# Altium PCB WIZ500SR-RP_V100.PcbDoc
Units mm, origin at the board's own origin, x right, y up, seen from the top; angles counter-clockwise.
Board outline 50 x 30 mm, 4 copper layers (Top Layer, Internal Plane 1, Internal Plane 2, Bottom Layer); 73 components, 72 nets, 294 pads, 204 vias.
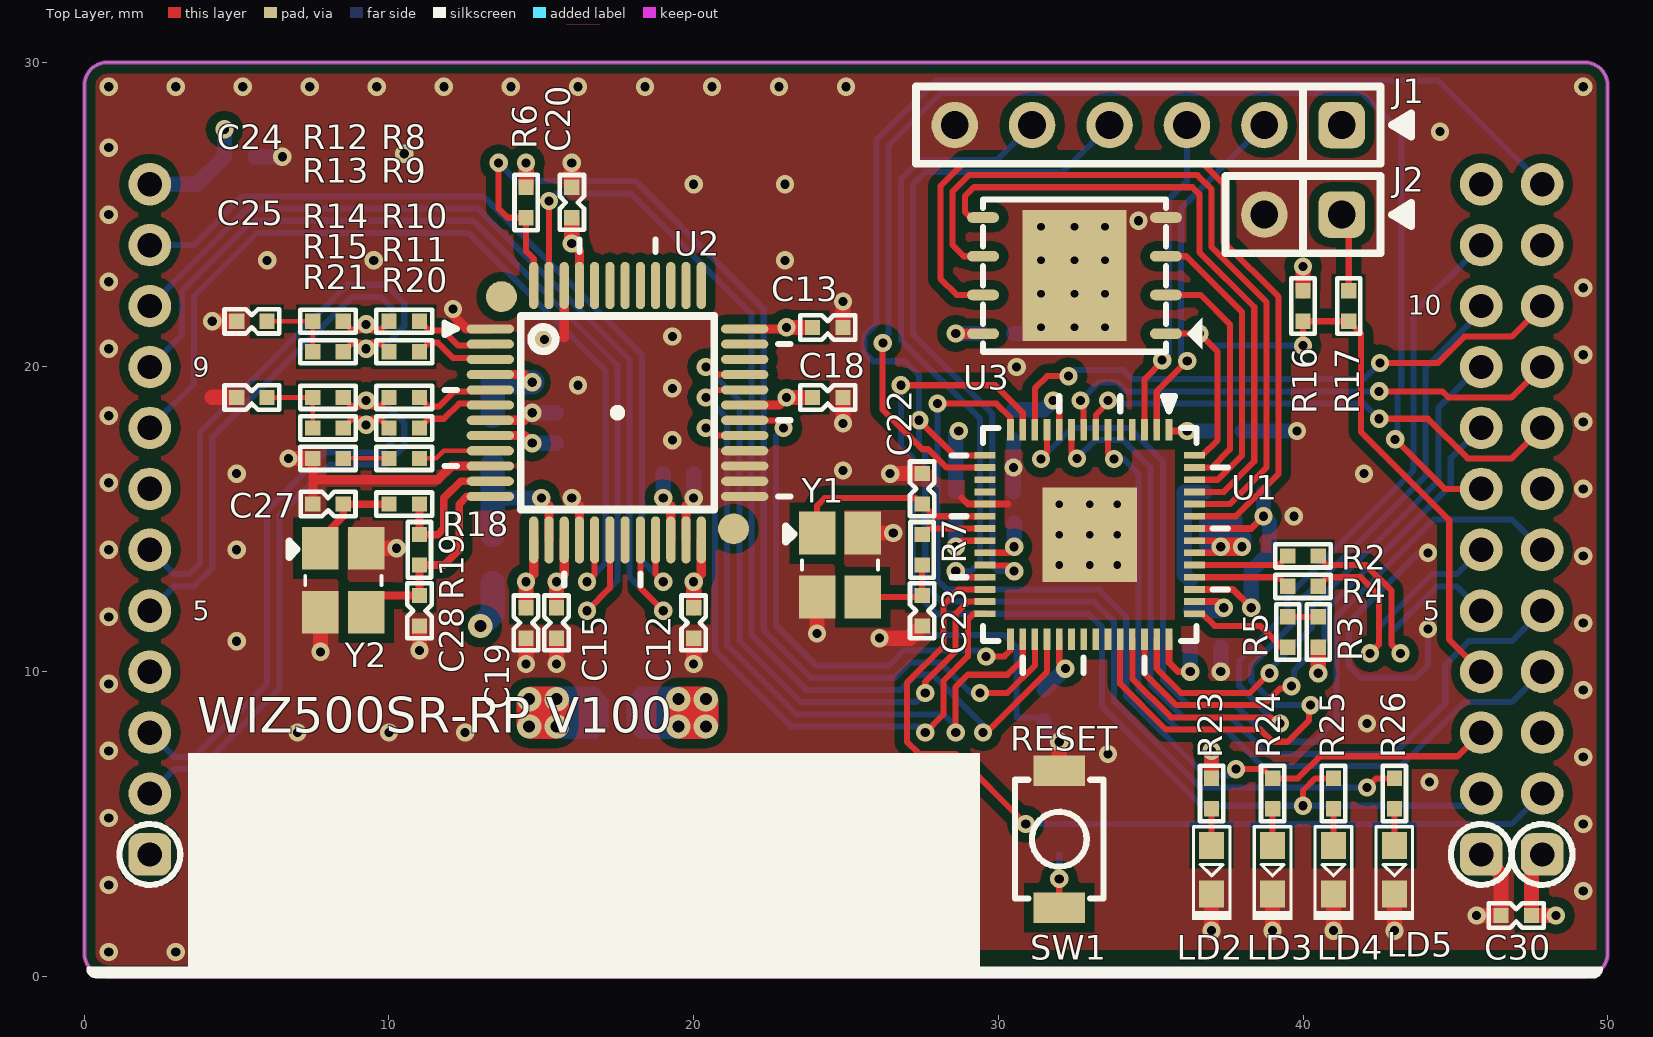
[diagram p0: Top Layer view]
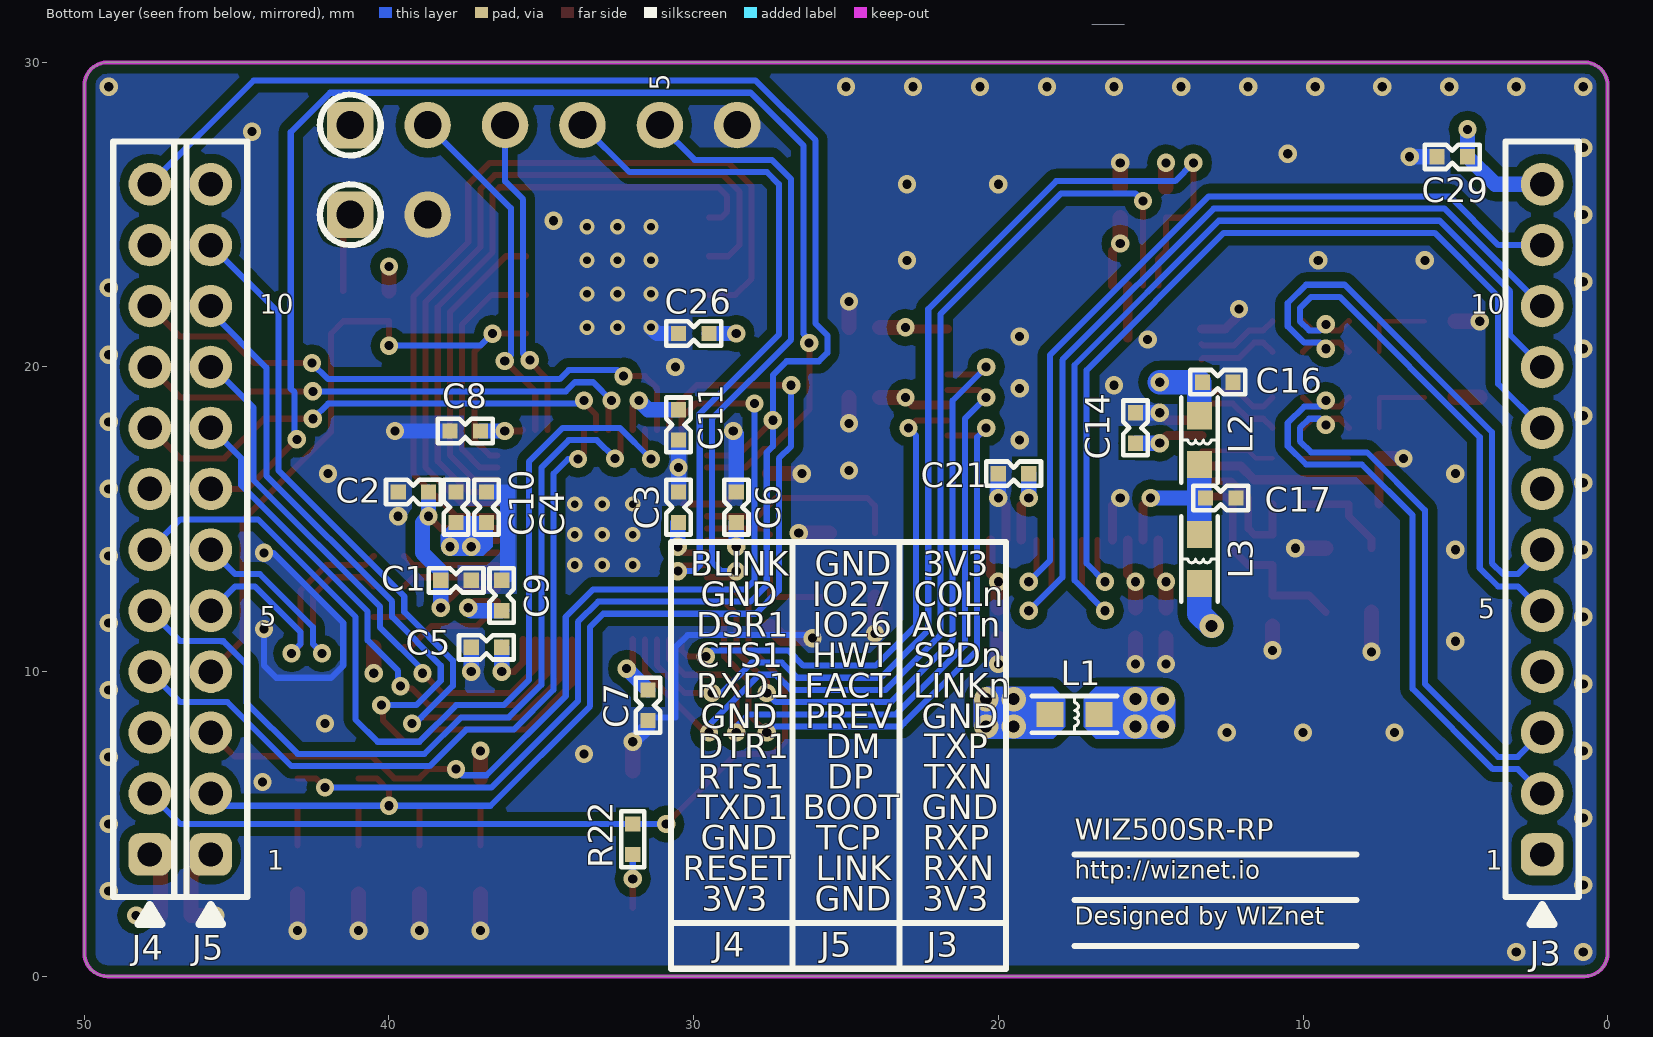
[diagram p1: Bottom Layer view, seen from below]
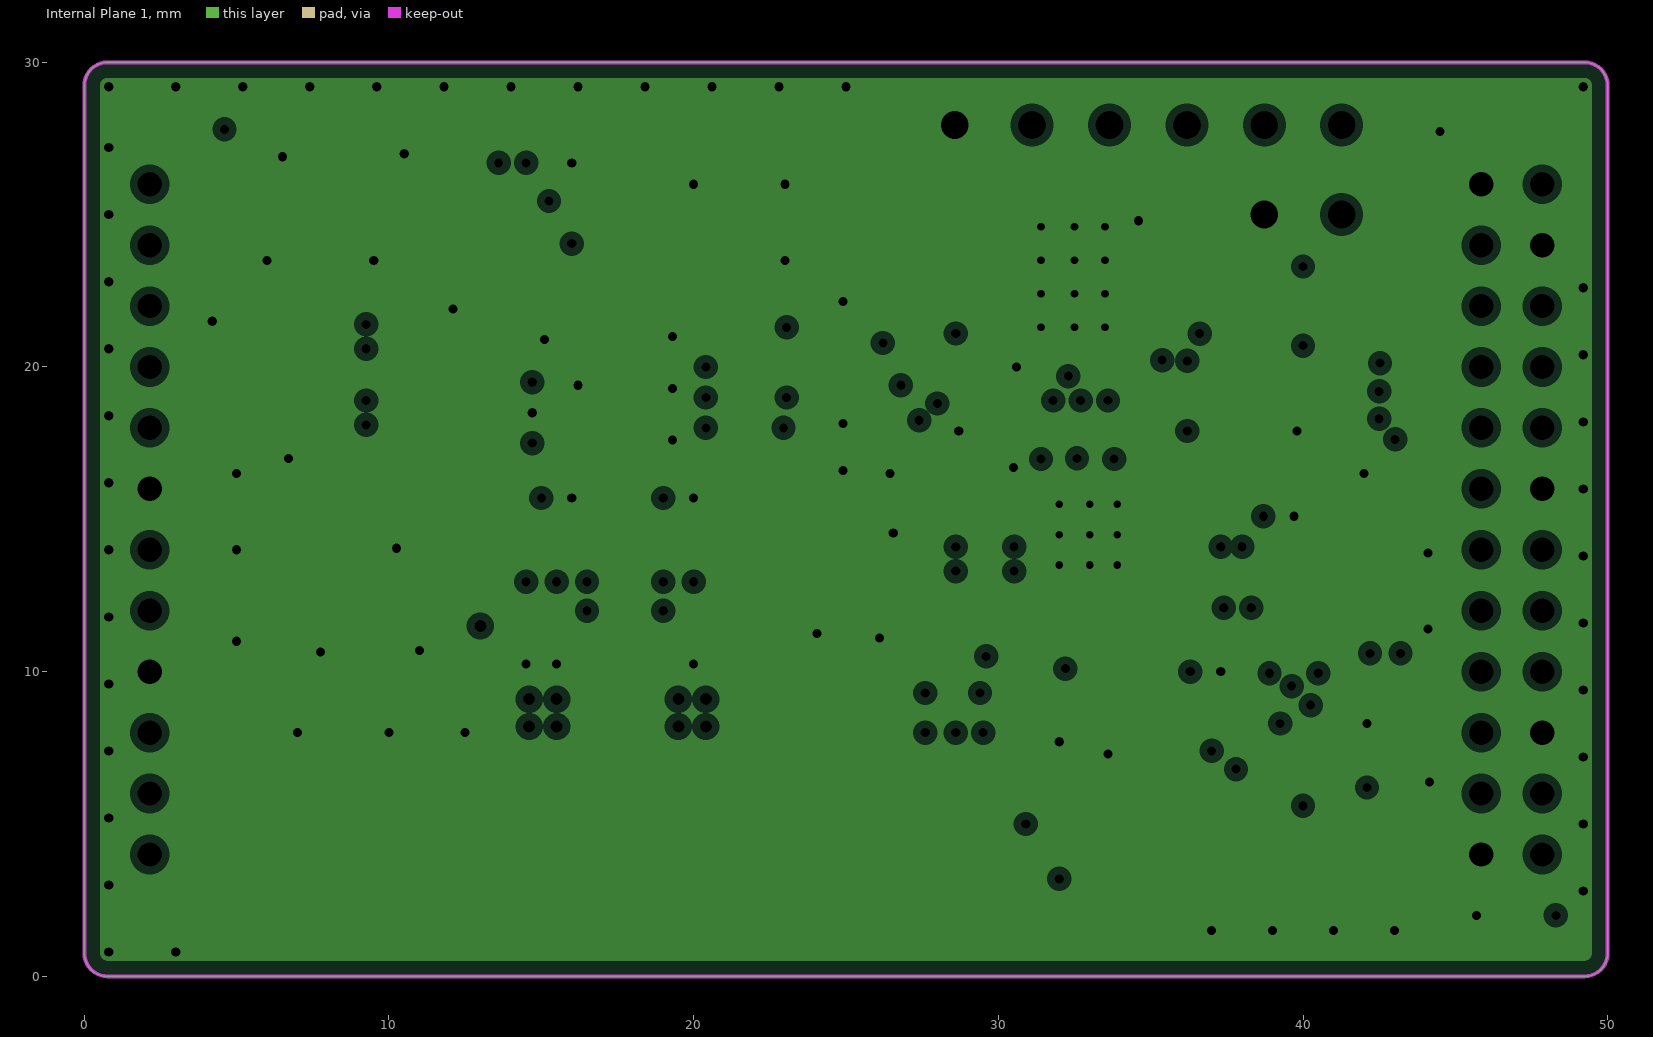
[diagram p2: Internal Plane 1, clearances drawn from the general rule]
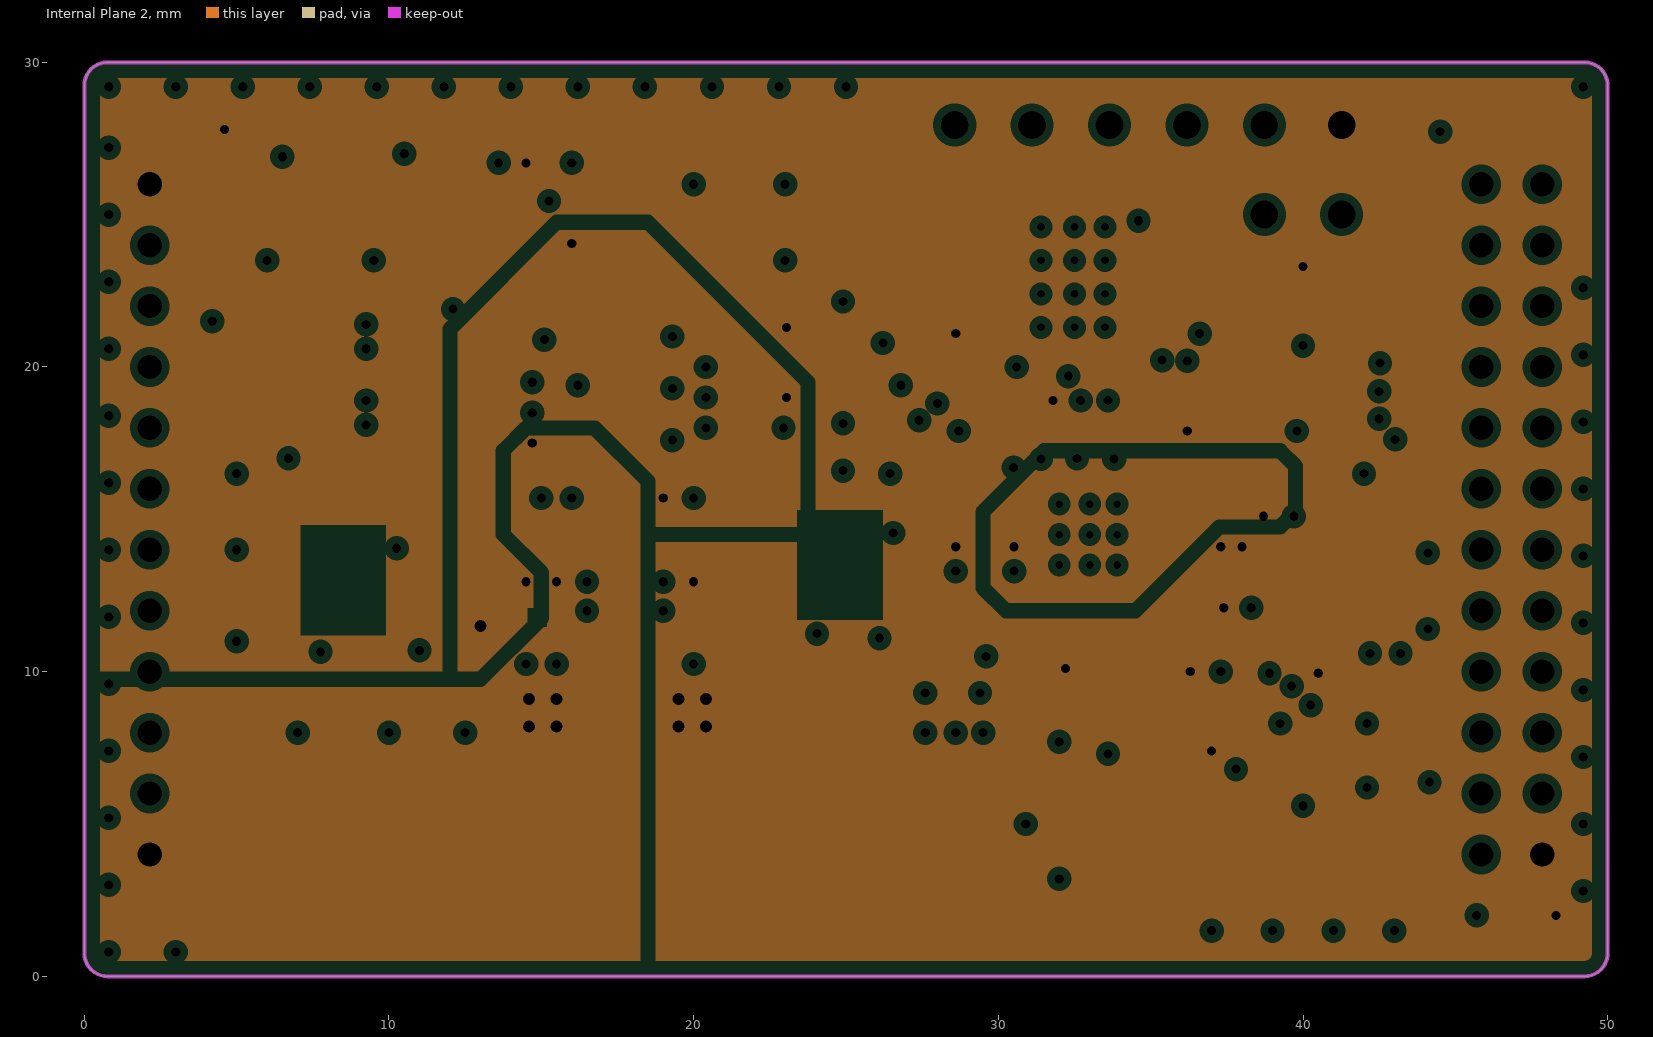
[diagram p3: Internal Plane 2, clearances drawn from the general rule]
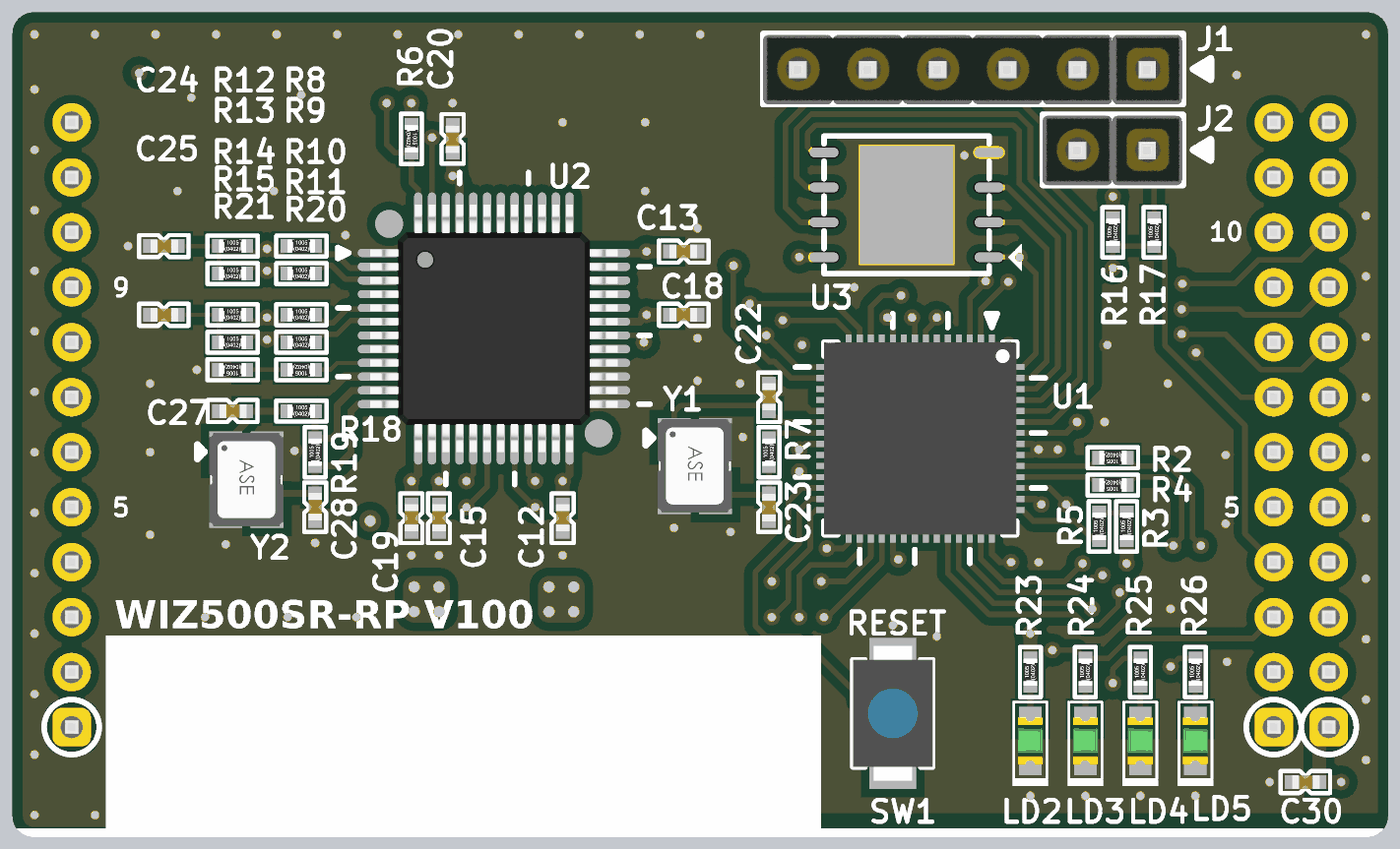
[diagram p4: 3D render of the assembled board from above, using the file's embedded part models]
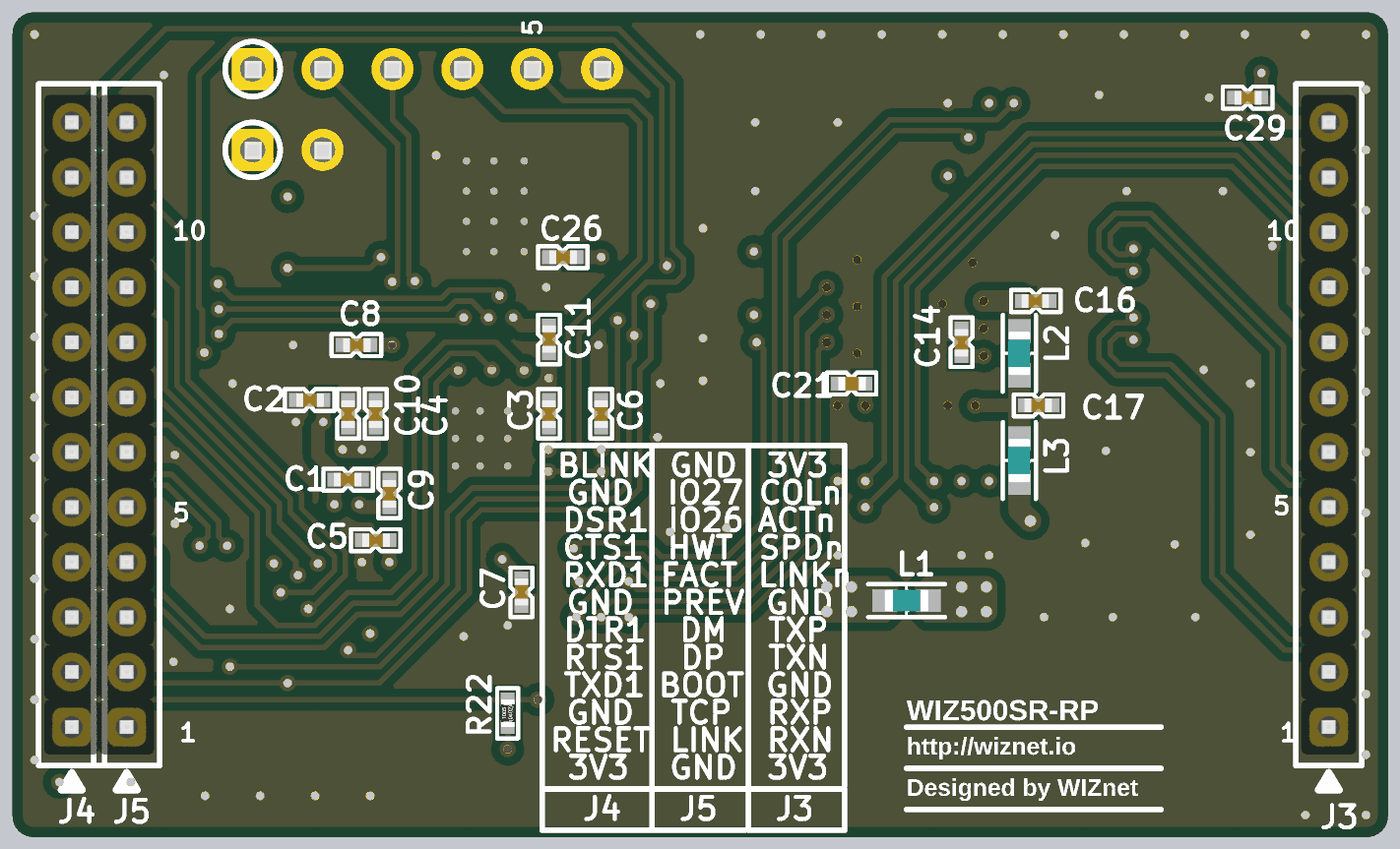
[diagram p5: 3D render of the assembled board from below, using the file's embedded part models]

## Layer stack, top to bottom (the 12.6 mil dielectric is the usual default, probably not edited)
Top Solder: solder mask 0.0102, Solder Resist, Dk 3.5
Top Layer: signal copper 0.0356
Dielectric1: core 0.32, FR-4, Dk 4.8
Internal Plane 1: plane copper 0.0356, net GND
Dielectric5: prepreg 0.32, FR-4, Dk 4.8
Internal Plane 2: plane copper 0.0356, net (Multiple Nets)
Dielectric6: core 0.32, FR-4, Dk 4.8
Bottom Layer: signal copper 0.0356
Bottom Solder: solder mask 0.0102, Solder Resist, Dk 3.5

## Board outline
0,0.762 0,29.238 cw(c0.762,29.238) 0.762,30 49.238,30 cw(c49.238,29.238) 50,29.238 50,0.762 cw(c49.238,0.762) 49.238,0 0.762,0 cw(c0.762,0.762)

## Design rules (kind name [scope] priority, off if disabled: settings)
Clearance U1 [InComponent('u1')] p1: gap=0.15 ignorepadtopadclearanceinfootprint=FALSE except(0: Arc-Hole Track-Hole SMDPad-Hole THPad-Hole Via-Hole Fill-Hole Poly-Hole Region-Hole Text-Hole; 0.3: Arc-Poly Track-Poly SMDPad-Poly THPad-Poly Via-Poly Fill-Poly Poly-Poly Poly-Region Poly-Text)
Clearance [All] p2: gap=0.2 ignorepadtopadclearanceinfootprint=FALSE except(0: Arc-Hole Track-Hole SMDPad-Hole THPad-Hole Via-Hole Fill-Hole Poly-Hole Region-Hole Text-Hole; 0.3: Arc-Poly Track-Poly SMDPad-Poly THPad-Poly Via-Poly Fill-Poly Poly-Poly Poly-Region Poly-Text)
DiffPairsRouting [All] p1: maxlimit=0.2 minlimit=0.2 mostfreqgap=0.2 toplayer_minwidth=0.2 toplayer_maxwidth=0.2 toplayer_prefwidth=0.2 bottomlayer_minwidth=0.2 bottomlayer_maxwidth=0.2 bottomlayer_prefwidth=0.2 maxuncoupledlength=15.24
HoleSize [All] p1: absolutevalues=TRUE maxlimit=4.064 minlimit=0.025 maxpercent=80.000 minpercent=20.000
PlaneClearance [All] p1: clearance=0.25
PlaneConnect [All] p1: planeconnectstyle=Direct reliefexpansion=0.508 reliefentries=4 reliefconductorwidth=0.254 reliefairgap=0.254
PolygonConnect [All] p1: connectstyle=Direct reliefconductorwidth=0.254 reliefentries=4 polygonreliefangle="90 Angle" airgapwidth=0.254
RoutingVias [All] p1: holewidth=0.3 width=0.6 viastyle="Through Hole" minholewidth=0.25 minwidth=0.5 maxholewidth=0.4 maxwidth=0.8
SolderMaskExpansion [All] p1: expansion=0 istentingtop=FALSE
Width [All] p1: maxlimit=6 minlimit=0.1 preferedwidth=0.2
26 further rules are at their usual default settings.

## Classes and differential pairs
differential pair TX: +TX_P -TX_N
differential pair RX: +RX_P -RX_N

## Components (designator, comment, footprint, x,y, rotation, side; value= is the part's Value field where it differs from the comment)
C1 "1uF" CAP-0402#1 37.8,13 r0 bottom
C2 "0.1uF" CAP-0402#1 39.2,15.9 r180 bottom
C3 "0.1uF" CAP-0402#1 30.5,15.4 r270 bottom
C4 "1uF" CAP-0402#1 36.8,15.4 r270 bottom
C5 "0.1uF" CAP-0402#1 36.8,10.8 r180 bottom
C6 "0.1uF" CAP-0402#1 28.6,15.4 r270 bottom
C7 "0.1uF" CAP-0402#1 31.5,8.9 r90 bottom
C8 "0.1uF" CAP-0402#1 37.5,17.9 r180 bottom
C9 "0.1uF" CAP-0402#1 36.3,12.5 r270 bottom
C10 "0.1uF" CAP-0402#1 37.8,15.4 r270 bottom
C11 "0.1uF" CAP-0402#1 30.5,18.1 r90 bottom
C12 "0.1uF" CAP-0402#1 20,11.6 r90 top
C13 "0.1uF" CAP-0402#1 24.4,21.3 r180 top
C14 "0.1uF" CAP-0402#1 15.5,18 r270 bottom
C15 "0.1uF" CAP-0402#1 15.5,11.6 r90 top
C16 "0.1uF" CAP-0402#1 12.8,19.5 r0 bottom
C17 "1uF" CAP-0402#1 12.7,15.7 r0 bottom
C18 "0.1uF" CAP-0402#1 24.4,19 r180 top
C19 "0.1uF" CAP-0402#1 14.5,11.6 r90 top
C20 "0.1uF" CAP-0402#1 16,25.4 r270 top
C21 "0.1uF" CAP-0402#2 19.5,16.5 r180 bottom
C22 "15pF" CAP-0402#1 27.5,16 r90 top
C23 "15pF" CAP-0402#1 27.5,12 r270 top
C24 "0.1uF" CAP-0402#1 5.5,21.5 r0 top
C25 "0.1uF" CAP-0402#1 5.5,19 r0 top
C26 "0.1uF" CAP-0402#1 30,21.1 r180 bottom
C27 "18pF" CAP-0402#1 8,15.5 r0 top
C28 "18pF" CAP-0402#1 11,12 r90 top
C29 "0.1uF" CAP-0402#1 5.1,26.9 r180 bottom
C30 "0.1uF" CAP-0402#1 47,2 r0 top
J1 "2.54mm 1x6 Pin Header DIP" IDC-1X6 41.27,27.94 r180 top
J2 "2.54mm 1x2 Pin Header DIP" IDC-1X2 41.27,25 r180 top
J3 "2.00mm 1x12 Pin Header DIP" IDC-1X12(2MM) 2.15,4 r90 bottom locked
J4 "2.00mm 1x12 Pin Header DIP" IDC-1X12(2MM) 47.85,4 r90 bottom locked
J5 "2.00mm 1x12 Pin Header DIP" IDC-1X12(2MM) 45.85,4 r90 bottom locked
L1 "HH-1M1608-121JT" IND-0603 17.5,8.6 r180 bottom
L2 "HH-1M1608-121JT" IND-0603 13.4,17.6 r270 bottom
L3 "HH-1M1608-121JT" IND-0603 13.4,13.7 r270 bottom
LD2 "Red" LED-0603-green 37,3.5 r270 top
LD3 "Green" LED-0603-GREEN 39,3.5 r270 top
LD4 "Green" LED-0603-GREEN 41,3.5 r270 top
LD5 "Green" LED-0603-GREEN 43,3.5 r270 top
R2 "0R" RES-0402#1 40,13.8 r180 top
R3 "200R" RES-0402#1 40.5,11.3 r90 top
R4 "0R" RES-0402#1 40,12.8 r180 top
R5 "1R" RES-0402#1 39.5,11.3 r90 top
R6 "4.7K" RES-0402#1 14.5,25.4 r270 top
R7 "1K" RES-0402#1 27.5,14 r90 top
R8 "3.3R" RES-0402#1 10.5,21.5 r0 top
R9 "3.3R" RES-0402#1 10.5,20.5 r0 top
R10 "3.3R" RES-0402#1 10.5,19 r0 top
R11 "3.3R" RES-0402#1 10.5,18 r0 top
R12 "49.9R" RES-0402#1 8,21.5 r0 top
R13 "49.9R" RES-0402#1 8,20.5 r0 top
R14 "49.9R" RES-0402#1 8,19 r0 top
R15 "49.9R" RES-0402#1 8,18 r0 top
R16 "NC" RES-0402#1 40,22 r90 top
R17 "1K" RES-0402#1 41.5,22 r90 top
R18 "0R" RES-0402#1 10.5,15.5 r0 top
R19 "1M" RES-0402#1 11,14 r90 top
R20 "12K/1%" RES-0402#1 10.5,17 r180 top
R21 "300R" RES-0402#1 8,17 r180 top
R22 "1K" RES-0402#1 32,4.5 r90 bottom
R23 "470R" RES-0402#1 37,6 r90 top
R24 "470R" RES-0402#2 39,6 r90 top
R25 "470R" RES-0402#2 41,6 r90 top
R26 "470R" RES-0402#2 43,6 r90 top
SW1 "1185SA(2.0)" ST-1185S 32,4.5 r90 top
U1 "RP2040" QFN56(0.4/7X7) 33,14.5 r270 top
U2 "W5100S" LQFP48(0.5/9.0) 17.5,18.5 r0 top
U3 "W25Q16JVZPIM" WSON8(6X5_1.27) 32.5,23 r180 top
Y1 "12MHz" OSC-TZ1067B 24.8,13.5 r270 top
Y2 "25MHz" OSC-82J0626 8.5,13 r270 top

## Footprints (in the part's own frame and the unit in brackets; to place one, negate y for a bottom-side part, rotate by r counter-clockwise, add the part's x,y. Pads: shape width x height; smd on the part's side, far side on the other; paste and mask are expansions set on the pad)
CAP-0402#1 [mm]
  rect 0.5x0.5 smd: 1(-0.5,0) 2(0.5,0)
  silkscreen extent -0.9,-0.4 0.9,0.4, body extent -0.48,-0.25 0.52,0.25, height 0.6
CAP-0402#2 [mm] "Ceramic CAP 0402(1005)"
  rect 0.5x0.5 smd: 1(-0.5,-0.004) 2(0.5,-0.004)
  silkscreen extent -0.9,-0.4 0.9,0.4, body extent -0.48,-0.25 0.52,0.25, height 0.6
IDC-1X2 [mil]
  rrect50% 60x60 hole 36: 1(0,0)
  round 60 hole 36: 2(100,0)
  silkscreen extent -90,-50 150,50, body extent -49,-49 151,51, height 336
IDC-1X6 [mil] "6-Way 2.54 mm Male Header"
  rrect50% 60x60 hole 36: 1(0,0)
  round 60 hole 36: 2(100,0) 3(200,0) 4(300,0) 5(400,0) 6(500,0)
  silkscreen extent -90,-50 550,50, body extent -49,-49 551,51, height 336
IDC-1X12(2MM) [mil]
  rrect50% 55x55 hole 31.5: 1(0,0)
  round 55 hole 31.5: 2(78.74,0) 3(157.48,0) 4(236.22,0) 5(314.96,0) 6(393.7,0) 7(472.44,0) 8(551.18,0) 9(629.92,0) 10(708.66,0) 11(787.4,0) 12(866.14,0)
  silkscreen extent -90,-47 921,47, body extent -39,-39 906,39, height 217
IND-0603 [mm] "Inductor 0603(1608)"
  rect 0.89x0.82 smd: 1(-0.8,0) 2(0.8,0)
  silkscreen extent -1.4,-0.6 1.4,0.6, body extent -0.8,-0.4 0.8,0.4, height 0.95
LED-0603-green [mm] "LED-0603-GREEN"
  rect 0.89x0.82 smd: 1(-0.8,0) 2(0.8,0)
  silkscreen extent -1.41,-0.65 1.65,0.65, body extent -0.85,-0.45 0.85,0.45, height 0.9
LED-0603-GREEN [mm] "LED-0603-GREEN"
  rect 0.89x0.82 smd: 1(-0.8,0) 2(0.8,0)
  silkscreen extent -1.41,-0.65 1.65,0.65, body extent -0.85,-0.45 0.85,0.45, height 0.9
LQFP48(0.5/9.0) [mm]
  round 1.016 smd: 0(-3.81,3.81) 0(3.81,-3.81)
  oval 1.55x0.3 smd: 1(-4.175,2.75) 2(-4.175,2.25) 3(-4.175,1.75) 4(-4.175,1.25) 5(-4.175,0.75) 6(-4.175,0.25) 7(-4.175,-0.25) 8(-4.175,-0.75) 9(-4.175,-1.25) 10(-4.175,-1.75) 11(-4.175,-2.25) 12(-4.175,-2.75) 25(4.175,-2.75) 26(4.175,-2.25) 27(4.175,-1.75) 28(4.175,-1.25) 29(4.175,-0.75) 30(4.175,-0.25) 31(4.175,0.25) 32(4.175,0.75) 33(4.175,1.25) 34(4.175,1.75) 35(4.175,2.25) 36(4.175,2.75)
  oval 0.3x1.55 smd: 13(-2.75,-4.175) 14(-2.25,-4.175) 15(-1.75,-4.175) 16(-1.25,-4.175) 17(-0.75,-4.175) 18(-0.25,-4.175) 19(0.25,-4.175) 20(0.75,-4.175) 21(1.25,-4.175) 22(1.75,-4.175) 23(2.25,-4.175) 24(2.75,-4.175) 37(2.75,4.175) 38(2.25,4.175) 39(1.75,4.175) 40(1.25,4.175) 41(0.75,4.175) 42(0.25,4.175) 43(-0.25,4.175) 44(-0.75,4.175) 45(-1.25,4.175) 46(-1.75,4.175) 47(-2.25,4.175) 48(-2.75,4.175)
  silkscreen extent -5.67,-5.67 5.68,5.68, body extent -4.5,-4.5 4.5,4.5, height 1.5
OSC-82J0626 [mm]
  rect 1.4x1.2 smd: 1(-1.05,-0.75) 2(1.05,-0.75) 3(1.05,0.75) 4(-1.05,0.75)
  silkscreen extent -1.27,-1.78 0.15,1.25, body extent -1.7,-1.35 1.7,1.35, height 1.06
OSC-TZ1067B [mm]
  rect 1.4x1.2 smd: 1(-1.05,-0.75) 2(1.05,-0.75) 3(1.05,0.75) 4(-1.05,0.75)
  silkscreen extent -1.27,-1.78 0.15,1.25, body extent -1.7,-1.35 1.7,1.35, height 1.06
QFN56(0.4/7X7) [mm]
  rect 0.7x0.22 smd: 1(-3.44,2.6) 2(-3.44,2.2) 3(-3.44,1.8) 4(-3.44,1.4) 5(-3.44,1) 6(-3.44,0.6) 7(-3.44,0.2) 8(-3.44,-0.2) 9(-3.44,-0.6) 10(-3.44,-1) 11(-3.44,-1.4) 12(-3.44,-1.8) 13(-3.44,-2.2) 14(-3.44,-2.6) 29(3.44,-2.6) 30(3.44,-2.2) 31(3.44,-1.8) 32(3.44,-1.4) 33(3.44,-1) 34(3.44,-0.6) 35(3.44,-0.2) 36(3.44,0.2) 37(3.44,0.6) 38(3.44,1) 39(3.44,1.4) 40(3.44,1.8) 41(3.44,2.2) 42(3.44,2.6)
  rect 0.22x0.7 smd: 15(-2.6,-3.44) 16(-2.2,-3.44) 17(-1.8,-3.44) 18(-1.4,-3.44) 19(-1,-3.44) 20(-0.6,-3.44) 21(-0.2,-3.44) 22(0.2,-3.44) 23(0.6,-3.44) 24(1,-3.44) 25(1.4,-3.44) 26(1.8,-3.44) 27(2.2,-3.44) 28(2.6,-3.44) 43(2.6,3.44) 44(2.2,3.44) 45(1.8,3.44) 46(1.4,3.44) 47(1,3.44) 48(0.6,3.44) 49(0.2,3.44) 50(-0.2,3.44) 51(-0.6,3.44) 52(-1,3.44) 53(-1.4,3.44) 54(-1.8,3.44) 55(-2.2,3.44) 56(-2.6,3.44)
  rect 3.1x3.1 smd: 57(0,0)
  silkscreen extent -4.54,-4.54 4.54,4.54, body extent -3.5,-3.5 3.5,3.5, height 0.8
RES-0402#1 [mm]
  rect 0.5x0.5 smd: 1(-0.5,0) 2(0.5,0)
  silkscreen extent -0.91,-0.38 0.91,0.38, body extent -0.5,-0.25 0.5,0.25, height 0.35
RES-0402#2 [mm]
  rect 0.5x0.5 smd: 1(-0.5,-0.004) 2(0.5,-0.004)
  silkscreen extent -0.91,-0.38 0.91,0.38, body extent -0.5,-0.25 0.5,0.25, height 0.35
ST-1185S [mm]
  rect 1x1.7 smd: 1(-2.25,0) 2(2.25,0)
  silkscreen extent -1.95,-1.45 1.95,1.45, body extent -2.45,-1.45 2.45,1.45, height 2
WSON8(6X5_1.27) [mm]
  oval 1.05x0.35 smd mask+0.05: 1(-3,1.905) 2(-3,0.635) 3(-3,-0.635) 4(-3,-1.905) 5(3,-1.905) 6(3,-0.635) 7(3,0.635) 8(3,1.905)
  rect 3.4x4.3 smd mask+0.05: 9(0,0)
  silkscreen extent -4.2,-2.5 3,2.5, body extent -3,-2.5 3,2.5, height 0.8

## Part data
C1 C2 C3 C4 C5 C6 C7 C8 C9 C10 C11 C12 C13 C14 C15 C16 C17 C18 C19 C20 C21 C22 C23 C24 C25 C26 C27 C28 C29 C30: library part CAP-0402, "Ceramic CAP 0402(1005)"
L1 L2 L3: library part IND-0603, "Inductor 0603(1608)"
LD2 LD3 LD4 LD5: library part LED-0603, "LED-0603"
R2 R3 R4 R5 R6 R7 R8 R9 R10 R11 R12 R13 R14 R15 R16 R17 R18 R19 R20 R21 R22 R23 R24 R25 R26: library part RES-0402, "RES-0402"
SW1: library part ITS-1107(SMD), "TACT Switch (SMD)"
U1: "Raspverry Pi, Dual ARM Cortex-M0+ @ 133MHz"
U2: "WIZnet Hardwired TCP/IP Chip"
U3: "3V 16M-BIT / SERIAL FLASH MEMORY WITH / DUAL/QUAD SPI, QPI & DTR"
Y1: library part OSC-TZ1067B-12MHz, "X-tal 12MHz,3.2x2.5 SMD, CL=20pF"
Y2: library part OSC-82J0626-25MHz, "X-tal 25MHz,3.2x2.5 SMD, CL=18pF"

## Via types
v1: diameter 0.6, hole 0.3, Top Layer to Bottom Layer, tented both sides, 174 vias
v2: diameter 0.5, hole 0.25, Top Layer to Bottom Layer, tented both sides, 21 vias
v3: diameter 0.8, hole 0.4, Top Layer to Bottom Layer, tented both sides, 9 vias

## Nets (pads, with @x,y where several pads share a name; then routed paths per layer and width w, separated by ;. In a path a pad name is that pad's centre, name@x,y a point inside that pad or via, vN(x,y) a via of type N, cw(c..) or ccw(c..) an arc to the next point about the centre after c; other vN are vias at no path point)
1V1: C1.2 C2.2 C3.2 U1.23 U1.45 U1.50 | length 10.5
  Top Layer w0.22: U1.23 30.32,13.9 v1(30.52,14.1) ; U1.45 37.7,12.7 v1(38.3,12.1) ; U1.50 38.3,14.7 v1(38.7,15.1)
  Bottom Layer w0.5: C3.2 30.52,14.88 v1(30.52,14.1) ; v1(38.3,12.1) C1.2 38.3,13.3 38.9,13.9 38.9,14.9 v1(38.7,15.1) C2.2
1V2A: C16.2 L2.1 U2.4 | length 3.9
  Top Layer w0.3: U2.4 14.45,19.75 v1(14.7,19.5)
  Bottom Layer w0.8: L2.1 13.4,19.5 v1(14.7,19.5)
1V2D: C18.2 C19.2 C20.2 C21.2 L3.2 U2.13 U2.22 U2.31 U2.45 | length 10.8
  Top Layer w0.3: v1(14.5,12.95) 14.75,13.2 U2.13 ; v1(16,24.05) 16.25,23.8 U2.45 ; v1(19,15.7) 19.25,15.45 U2.22 ; U2.31 22.8,18.75 v1(23.05,19)
  Top Layer w0.5: C19.2 v1(14.5,12.95) ; v1(16,24.05) C20.2 ; v1(23.05,19) C18.2
  Bottom Layer w0.5: v1(19,15.7) C21.2
  Bottom Layer w0.8: v3(13,11.5) 13.4,11.9 L3.2
1V2O: C17.2 L2.2 L3.1 U2.14 | length 5.4
  Top Layer w0.3: v1(15,15.7) 15.25,15.45 U2.14
  Bottom Layer w0.5: C17.2@13.4,15.7 v1(15,15.7)
  Bottom Layer w0.8: L3.1 13.4,15.7 L2.2
3V3: C4.2 C5.2 C6.2 C7.2 C8.2 C9.2 C10.2 C11.2 C12.2 C13.2 C26.2 C29.2 C30.2 J1.1 J3.12 J4.1 L1.1 R3.1 R6.1 R16.2 R23.2 U1.1 U1.10 U1.22 U1.33 U1.42 U1.44 U1.48 U1.49 U2.24 U2.36 U3.8 | length 32
  Top Layer w0.2: U1.1 U1.1@35.64,17.9
  Top Layer w0.22: v1(28.6,14.1) 28.8,14.3 U1.22 ; v1(31.8,18.9) 32,18.7 U1.10 ; U1.33 32,10.3 v1(32.2,10.1) ; U1.42 35.6,10.3 35.9,10 v1(36.3,10) ; U1.1@35.64,17.9 v1(36.2,17.9) ; U1.44 37.2,12.3 v1(37.4,12.1) ; U1.48 37.1,13.9 v1(37.3,14.1) 37.1,14.3 U1.49
  Top Layer w0.3: v1(20,12.95) 20.25,13.2 U2.24 ; U2.36 23,21.25 v1(23.05,21.3)
  Top Layer w0.35: v1@28.6,21.095 U3.8
  Top Layer w0.5: C12.2 v1(20,12.95) ; v1(23.05,21.3) C13.2 ; R23.2 v1(37,7.4) ; R16.2 v1(40,23.3) ; v1(40.5,9.95) R3.1 ; J4.1 47.5,3.65 C30.2 v1(48.3,2)
  Top Layer w0.508: R6.1 v1(14.5,26.7)
  Top Layer w0.6: v1(37.3,14.1) v1(38,14.1)
  Bottom Layer w0.5: J3.12 3.7,26 C29.2 v1(4.6,27.8) ; v1(28.6,14.1) C6.2 ; v1(28.6,21.1) C26.2 ; C11.2 31.5,18.6 v1(31.8,18.9) ; C7.2 v1(32.2,10.1) ; v1(36.2,17.9) C8.2 ; v1(36.3,10) C5.2 ; C9.2 37.3,12 v1(37.4,12.1)
  Bottom Layer w0.6: v1(37.3,14.1) v1(38,14.1)
  other v3: 19.5,8.2 20.4,8.2 19.5,9.1 20.4,9.1
3V3A: C14.2 C15.2 J3.1 L1.2 U2.8 U2.15 | length 4.6
  Top Layer w0.3: U2.8 14.45,17.75 v1(14.7,17.5) ; v1(15.5,12.95) 15.75,13.2 U2.15
  Top Layer w0.5: C15.2 v1(15.5,12.95)
  Bottom Layer w0.5: v1(14.7,17.5) C14.2
  other v3: 14.6,8.2 15.5,8.2 14.6,9.1 15.5,9.1
ACTn: J3.10 U2.20 | length 30.5
  Top Layer w0.2: U2.20 18.25,12.75 v1(19,12)
  Bottom Layer w0.2: J3.10 5.35,25.2 12.931,25.2 17.9,20.231 17.9,13.1 v1(19,12)
ADC_VREF: R3.2 R5.2 | length 1
  Top Layer w0.2: R5.2 R3.2
BLINK: J4.12 R26.2 U1.15 | length 62.7
  Top Layer w0.2: v1@27.475,18.25 27.475,18.175 28.55,17.1 U1.15 ; v1(42.1,6.2) 42.4,6.5 R26.2
  Bottom Layer w0.2: v1(42.1,6.2) 36.634,6.2 33.8,9.034 33.8,11.634 33.134,12.3 28.134,12.3 27.6,12.834 27.6,17.2 27.4,17.4 v1(27.4,18.25) 27.4,19.734 26.947,20.188 25.892,20.188 25.611,20.469 25.611,21.036 26,21.425 26,27.438 27.964,29.402 44.448,29.402 J4.12
BOOTSEL: J5.4 R16.1 R17.1 U1.56 U3.1 | length 25
  Top Layer w0.2: U3.1 v1(36.605,21.095) 37.2,20.5 37.2,17.6 36.7,17.1 U1.56 ; v1(40,20.7) R16.1 R17.1 41.9,21.1 41.9,17.875 44.8,14.975 44.8,11.05 J5.4
  Bottom Layer w0.2: v1(36.605,21.095) 37,20.7 v1(40,20.7)
COLn: J3.11 U2.21 | length 28.2
  Top Layer w0.2: U2.21 18.75,13.2 v1(19,12.95)
  Bottom Layer w0.2: J3.11 3.584,24 5.184,25.6 13.097,25.6 18.3,20.397 18.3,13.65 v1(19,12.95)
FACT_RST: J5.8 U1.40 | length 17.7
  Top Layer w0.2: U1.40 34.8,9.934 35.834,8.9 38.7,8.9 39.248,9.448 39.548,9.448 v1(39.625,9.525)
  Bottom Layer w0.2: v1(39.625,9.525) 39.702,9.602 39.702,10.027 40.7,11.025 40.7,11.975 44.85,16.125 44.85,17 J5.8
GND: C1.1 C2.1 C3.1 C4.1 C5.1 C6.1 C7.1 C8.1 C9.1 C10.1 C11.1 C12.1 C13.1 C14.1 C15.1 C16.1 C17.1 C18.1 C19.1 C20.1 C21.1 C22.2 C23.2 C24.1 C25.1 C26.1 C27.1 C28.1 C29.1 C30.1 J1.6 J2.2 J3.4 J3.7 J4.3 J4.7 J4.11 J5.1 J5.12 LD2.2 LD3.2 LD4.2 LD5.2 R21.2 SW1.2 U1.19 U1.57 U2.1 U2.7 U2.10 U2.16 U2.23 U2.25 U2.26 U2.27 U2.28 U2.46 U3.4 U3.9 Y1.2 Y1.4 Y2.2 Y2.4 | length 72.5
  Top Layer w0.22: 28.8,15.7 29,15.5 U1.19 30.32,15.5
  Top Layer w0.3: C27.1 7.5,16.3 ; R21.2 7.5,16.3 ; v1(12.1,21.9) 12.1,21.7 12.55,21.25 U2.1 ; U2.10 12.05,16.75 11.6,16.3 7.5,16.3 ; U2.7 14.45,18.25 v1(14.7,18.5) ; 15.75,20.95 U2.46 ; v1(16,15.7) 16.25,15.45 U2.16 ; U2.23 19.75,15.45 v1(20,15.7)
  Top Layer w0.5: v1(6.7,17) R21.2 ; v1(7.75,10.65) Y2.2 ; Y2.4 v1(10.25,14.05) ; v1(11,10.7) C28.1 ; v1(14.5,10.25) C19.1 ; v1(15.5,10.25) C15.1 ; v1(20,10.25) C12.1 ; v1(24.05,11.25) Y1.2 ; v1(24.9,18.15) C18.1 ; C13.1 v1(24.9,22.15) ; Y1.4 v1(26.55,14.55) ; v1(26.1,11.1) 27.1,11.1 C23.2 ; v1(26.45,16.5) C22.2 ; SW1.2 v1(32,7.7) ; v1(37,1.5) LD2.2 ; v1(39,1.5) LD3.2 ; v1(41,1.5) LD4.2 ; v1(43,1.5) LD5.2 ; v1(45.7,2) C30.1 46.5,3.35 J5.1
  Top Layer w0.508: 4.2,19 C25.1 ; v1(4.2,21.5) C24.1 ; C20.1 v1(16,26.7)
  Bottom Layer w0.2: v1(26.1,11.1) 26.2,11.2 30.2,11.2 30.6,10.8 30.6,8.5 31.4,8.5 C7.1 ; v1(44.1,11.4) 44.1,10.2 43.7,9.8 41.9,9.8 41.5,10.2 41.5,11.6 43.8,13.9 v1(44.1,13.9)
  Bottom Layer w0.5: C29.1 v1(6.5,26.9) ; v1(14.7,18.5) C14.1 ; v1(20,15.7) C21.1 ; C6.1 28.6,17.8 v1(28.7,17.9) ; C3.1 v1(30.5,16.7) C11.1 ; C26.1 31.2,21.1 v2(31.4,21.3) ; C7.1 31.5,8.2 v1(32,7.7) ; C9.1 36.1,13.2 36.1,15.9 C4.1 ; v1(37.3,10) C5.1 ; C8.1 v1(39.8,17.9)
  other v1: 0.8,0.8 3,0.8 49.2,2.8 0.8,3 49.2,5 0.8,5.2 44.15,6.375 49.2,7.2 33.6,7.3 0.8,7.4 7,8 10,8 12.5,8 42.1,8.3 49.2,9.4 0.8,9.6 5,11 49.2,11.6 0.8,11.8 49.2,13.8 0.8,14 5,14 39.7,15.1 49.2,16 0.8,16.2 5,16.5 42,16.5 24.9,16.6 19.3,17.6 49.2,18.2 0.8,18.4 19.3,19.3 16.2,19.4 30.6,20 49.2,20.4 0.8,20.6 15.1,20.9 19.3,21 49.2,22.6 0.8,22.8 6,23.5 9.5,23.5 23,23.5 34.6,24.8 0.8,25 20,26 23,26 10.5,27 0.8,27.2 44.5,27.725 0.8,29.2 3,29.2 5.2,29.2 7.4,29.2 9.6,29.2 11.8,29.2 14,29.2 16.2,29.2 18.4,29.2 20.6,29.2 22.8,29.2 25,29.2 49.2,29.2
  other v2: 32,13.5 33,13.5 33.9,13.5 32,14.5 33,14.5 33.9,14.5 32,15.5 33,15.5 33.9,15.5 32.5,21.3 33.5,21.3 31.4,22.4 32.5,22.4 33.5,22.4 31.4,23.5 32.5,23.5 33.5,23.5 31.4,24.6 32.5,24.6 33.5,24.6
GPIO26/ADC0: J5.10 U1.38 | length 27.1
  Top Layer w0.2: U1.38 34,9.603 35.503,8.1 38.6,8.1 39,7.7 39.497,7.7 40.2,8.403 40.2,8.775 v1@40.3,8.875
  Bottom Layer w0.2: v1(40.25,8.9) 39.101,8.9 38.3,9.701 38.3,10.199 39.9,11.799 39.9,12.306 44.025,16.431 44.025,19.975 45.775,21.725 J5.10@45.775,22.2
GPIO27/ADC1: J5.11 U1.39 | length 26.3
  Top Layer w0.2: U1.39 34.4,10.894 34.4,9.769 35.669,8.5 38.94,8.5 39.19,8.25 v1@39.2,8.25
  Bottom Layer w0.2: v1(39.249,8.3) 39.14,8.3 38.94,8.5 38.936,8.5 37.9,9.536 37.9,10.364 39.5,11.964 39.5,12.472 43.625,16.597 43.625,21.775 45.65,23.8 J5.11@45.65,24
HW_TRIG: J5.9 U1.41 | length 18.1
  Top Layer w0.2: U1.41 35.2,10.1 36,9.3 38.25,9.3 v1@38.875,9.925
  Bottom Layer w0.2: v1(38.9,9.95) 38.9,10.058 40.3,11.458 40.3,12.141 44.45,16.291 44.45,18.675 J5.9@45.75,19.975
INTn: U1.32 U2.47 | length 35.2
  Top Layer w0.2: U2.47 v1(15.25,25.45) ; v1(29.5,8) 29.6,8 31.6,10 U1.32
  Bottom Layer w0.2: v1(15.25,25.45) 15.5,25.7 17.934,25.7 21.9,21.734 21.9,11.197 23.697,9.4 26.8,9.4 27.3,9.9 27.6,9.9 27.849,9.9 29.5,8.249 v1(29.5,8)
LINK_STATUS: J5.2 R25.2 U1.13 | length 36.8
  Top Layer w0.2: v1(26.8,19.4) 29.9,19.4 30.8,18.5 U1.13 ; v1(40,5.6) 40,6.1 40.4,6.5 R25.2
  Bottom Layer w0.2: v1(26.8,19.4) 26.8,17.4 27.2,17 27.2,12.669 27.969,11.9 32.969,11.9 33.4,11.469 33.4,8.869 36.669,5.6 45.45,5.6 J5.2
LINKn: J3.8 U2.17 | length 29.8
  Top Layer w0.2: v1(16.5,12.95) 16.75,13.2 U2.17
  Bottom Layer w0.2: J3.8 3.6,19.45 3.6,22.319 5.681,24.4 12.6,24.4 17.1,19.9 17.1,13.55 v1(16.5,12.95)
NetC23_1: C23.1 R7.1 Y1.3 | length 2.7
  Top Layer w0.2: Y1.3@25.65,12.45 C23.1@27.25,12.45 ; C23.1@27.45,12.45 C23.1 R7.1
NetC24_2: C24.2 R12.1 R13.1 | length 2.5
  Top Layer w0.152: C24.2 R12.1 R13.1
NetC25_2: C25.2 R14.1 R15.1 | length 2.5
  Top Layer w0.152: C25.2 R14.1 R15.1
NetC27_2: C27.2 R18.1 Y2.1 | length 3.3
  Top Layer w0.25: Y2.1 7.75,14.35 8.5,15.1 C27.2 R18.1
NetC28_2: C28.2 R19.1 U2.12 Y2.3 | length 7.1
  Top Layer w0.25: Y2.3 9.8,12.5 C28.2 R19.1 11.8,13.5 12.3,14 12.3,15.5 12.55,15.75 U2.12
NetJ2_1: J2.1 R17.2 | length 2.6
  Top Layer w0.2: J2.1 41.5,24.77 R17.2
NetLD2_1: LD2.1 R23.1 | length 1.2
  Top Layer w0.2: LD2.1 R23.1
NetLD3_1: LD3.1 R24.1 | length 1.2
  Top Layer w0.2: LD3.1 39.004,4.304 R24.1
NetLD4_1: LD4.1 R25.1 | length 1.2
  Top Layer w0.2: LD4.1 41,5.496 R25.1
NetLD5_1: LD5.1 R26.1 | length 1.2
  Top Layer w0.2: LD5.1 43,5.496 R26.1
NetR2_2: R2.2 U1.47 | length 3.2
  Top Layer w0.2: U1.47 39.2,13.5 R2.2
NetR4_2: R4.2 U1.46 | length 3.2
  Top Layer w0.2: U1.46 39.2,13.1 R4.2
NetR5_1: R5.1 U1.43 | length 3.5
  Top Layer w0.2: U1.43 36.7,11.9 37.1,11.5 38.6,11.5 39.3,10.8 R5.1
NetR8_2: R8.2 U2.2 | length 2.7
  Top Layer w0.2: R8.2 11.3,21.2 11.766,21.2 12.266,20.7 13.275,20.7 U2.2
NetR9_2: R9.2 U2.3 | length 2.7
  Top Layer w0.2: R9.2 11.3,20.8 11.6,20.8 12.1,20.3 13.275,20.3 U2.3
NetR10_2: R10.2 U2.5 | length 2.7
  Top Layer w0.2: R10.2 11.3,18.7 11.634,18.7 12.134,19.2 13.275,19.2 U2.5
NetR11_2: R11.2 U2.6 | length 2.7
  Top Layer w0.2: R11.2 11.3,18.3 11.8,18.3 12.3,18.8 13.275,18.8 U2.6
NetR18_2: R18.2 R19.2 U2.11 | length 4.6
  Top Layer w0.25: R18.2 R19.2 11.6,14.5 11.8,14.7 11.8,15.7 12.35,16.25 U2.11
NetR20_1: R20.1 U2.9 | length 2.4
  Top Layer w0.152: R20.1 11.55,17 11.8,17.25 U2.9
NetR20_2: R20.2 R21.1 | length 1.5
  Top Layer w0.152: R21.1 R20.2
NetR22_1: R22.1 SW1.1 | length 1.8
  Top Layer w0.2: SW1.1 v1(32,3.2)
  Bottom Layer w0.2: v1(32,3.2) R22.1
PREV_BANK: J5.7 U1.16 | length 44.6
  Top Layer w0.2: v1@26.15,20.775 26.2,20.725 26.2,18.601 27.501,17.3 27.7,17.3 28.3,16.7 U1.16 ; v1@26.175,20.752 v1(26.211,20.787) ; v1(43.025,17.625) 44.65,16 45.725,16 J5.7@45.75,15.975
  Bottom Layer w0.2: v1(26.211,20.787) 26.211,20.896 26.4,21.085 26.4,27.272 28.13,29.002 41.933,29.002 43.225,27.71 43.225,19.289 43.1,19.164 43.1,17.7 v1(43.025,17.625)
QSPI1_SCLK: U1.52 U3.6 | length 24.6
  Top Layer w0.2: U3.6 28.865,23.635 28.5,24 28.5,25.766 29.034,26.3 36.534,26.3 37,25.834 37,23.934 38.8,22.134 38.8,20 38.8,16.7 37.6,15.5 U1.52
QSPI1_SD0: U1.53 U3.5 | length 21
  Top Layer w0.2: U3.5 29.095,24.905 28.9,25.1 28.9,25.6 29.2,25.9 36.369,25.9 36.6,25.669 36.6,23.769 38.4,21.969 38.4,20 38.4,16.9 37.4,15.9 U1.53
QSPI1_SD1: U1.55 U3.2 | length 8
  Top Layer w0.2: U3.2 36.635,22.365 37.6,21.4 37.6,17.3 37,16.7 U1.55
QSPI1_SD2: U1.54 U3.3 | length 9.9
  Top Layer w0.2: U3.3 36.165,23.635 38,21.8 38,17.1 37.2,16.3 U1.54
QSPI1_SD3: U1.51 U3.7 | length 28.1
  Top Layer w0.2: U3.7 28.635,22.365 28.1,22.9 28.1,25.931 28.869,26.7 36.7,26.7 37.4,26 37.4,24.1 39.2,22.3 39.2,16.5 37.8,15.1 U1.51
RSTn: R6.2 U1.31 U2.48 | length 37.5
  Top Layer w0.2: v1(13.6,26.7) 13.6,25.2 13.9,24.9 R6.2 14.5,23.8 14.75,23.55 U2.48 ; v1(29.4,9.3) 30.3,9.3 31.2,10.2 U1.31
  Bottom Layer w0.2: v1(13.6,26.7) 14.2,26.1 18.1,26.1 22.3,21.9 22.3,11.363 23.863,9.8 26.6,9.8 27.1,10.3 28.1,10.3 29.1,9.3 v1(29.4,9.3)
RUN: J4.2 R22.2 U1.26 | length 28.9
  Top Layer w0.2: U1.26 28.7,12.7 28.2,12.2 28.2,10.831 27,9.631 27,7.7 27.4,7.3 28.6,7.3 v1(30.9,5)
  Bottom Layer w0.2: v1(30.9,5) 46.85,5 J4.2
RX_N: J3.2 R10.1 R14.2 | length 20.6
  Top Layer w0.2: R14.2 8.8,18.7 9.05,18.7 v1(9.25,18.9) 9.45,18.7 9.7,18.7 R10.1
  Bottom Layer w0.2: J3.2 2.95,6.8 3.766,6.8 6.4,9.434 6.4,15.134 8.066,16.8 9.9,16.8 10.5,17.4 10.5,18.166 9.966,18.7 9.45,18.7 v1(9.25,18.9)
RX_P: J3.3 R11.1 R15.2 | length 19.3
  Top Layer w0.2: R15.2 8.8,18.3 9.05,18.3 v1(9.25,18.1) 9.45,18.3 9.7,18.3 R11.1
  Bottom Layer w0.2: J3.3 2.95,7.2 3.6,7.2 6,9.6 6,15.3 7.9,17.2 9.734,17.2 10.1,17.566 10.1,18 9.8,18.3 9.45,18.3 v1(9.25,18.1)
SPDn: J3.9 U2.18 | length 31.3
  Top Layer w0.2: v1(16.5,12) 17.25,12.75 U2.18
  Bottom Layer w0.2: J3.9 3.2,21.05 3.2,22.484 5.516,24.8 12.766,24.8 17.5,20.066 17.5,13 v1(16.5,12)
SPI0_CSn: U1.28 U2.29 | length 21.7
  Top Layer w0.2: v1(20.4,18) 20.65,17.75 U2.29 ; v1(27.6,8) 28.2,8.6 28.2,9.7 29,10.5 29,11.7 29.2,11.9 U1.28
  Bottom Layer w0.2: v1(20.4,18) 20.7,17.7 20.7,10.7 23.1,8.3 23.2,8.2 27.4,8.2 v1(27.6,8)
SPI0_RX: U1.27 U2.33 | length 22
  Top Layer w0.2: v1(20.4,20) 20.65,19.75 U2.33 ; v1(27.6,9.3) 27.6,9.666 28.6,10.666 28.6,11.9 29,12.3 U1.27
  Bottom Layer w0.2: v1(20.4,20) 21.5,18.9 21.5,11.031 23.531,9 27.3,9 v1(27.6,9.3)
SPI0_SCK: U1.29 U2.30 | length 16.9
  Top Layer w0.2: U2.30 22.7,18.25 v1(22.95,18) ; v1(29.6,10.5) 30.2,10.5 30.4,10.7 U1.29
  Bottom Layer w0.2: v1(22.95,18) 22.7,17.75 22.7,11.528 24.028,10.2 26.4,10.2 26.9,10.7 29.4,10.7 v1(29.6,10.5)
SPI0_TX: U1.30 U2.32 | length 23.3
  Top Layer w0.2: v1(20.4,19) 20.65,19.25 U2.32 ; v1(28.6,8) 28.6,9.5 29,9.9 30.3,9.9 30.8,10.4 U1.30
  Bottom Layer w0.2: v1(20.4,19) 21.1,18.3 21.1,10.866 23.366,8.6 28.2,8.6 28.6,8.2 v1(28.6,8)
SWCLK: J1.4 U1.24 | length 22.7
  Top Layer w0.2: U1.24 29.726,13.5 29.736,13.49 30.33,13.49 v1(30.52,13.3)
  Bottom Layer w0.2: v1(30.52,13.3) 30,13.3 29.8,13.5 29.8,18.466 27.2,21.066 27.2,26 27.6,26.4 32.11,26.4 J1.4
SWDIO: J1.5 U1.25 | length 20.7
  Top Layer w0.2: v1(28.6,13.3) 28.8,13.1 U1.25
  Bottom Layer w0.2: v1(28.6,13.3) 29.1,13.3 29.4,13.6 29.4,18.3 26.8,20.9 26.8,26.166 27.434,26.8 29.97,26.8 J1.5
TCP_STATUS: J5.3 R24.2 U1.14 | length 31.6
  Top Layer w0.2: v1@28.025,18.8 29.934,18.8 30.4,18.334 U1.14 ; v1(37.8,6.8) 38.704,6.8 R24.2 39.834,6.5 40.559,7.225 45.075,7.225 45.7,7.85 J5.3@45.7,7.95
  Bottom Layer w0.2: v1@27.975,18.85 28,18.825 v1(28,18.8) 28,13 28.3,12.7 33.3,12.7 34.2,11.8 34.2,9.2 36.8,6.6 37.6,6.6 v1(37.8,6.8)
TX_N: J3.5 R8.1 R12.2 | length 18.3
  Top Layer w0.2: R12.2 8.8,21.2 9.05,21.2 v1(9.25,21.4) 9.45,21.2 9.7,21.2 R8.1
  Bottom Layer w0.2: J3.5 2.95,12.8 3.6,12.8 4.2,13.4 4.2,17.7 8.8,22.3 9.734,22.3 10.1,21.934 10.1,21.5 9.8,21.2 9.45,21.2 v1(9.25,21.4)
TX_P: J3.6 R9.1 R13.2 | length 19.6
  Top Layer w0.2: R13.2 8.8,20.8 9.05,20.8 v1(9.25,20.6) 9.45,20.8 9.7,20.8 R9.1
  Bottom Layer w0.2: J3.6 2.95,13.2 3.434,13.2 3.8,13.566 3.8,17.866 8.634,22.7 9.9,22.7 10.5,22.1 10.5,21.334 9.966,20.8 9.45,20.8 v1(9.25,20.6)
UART0_RX: J1.3 U1.3 | length 10.6
  Top Layer w0.2: U1.3 34.8,19.6 35.4,20.2 v1(35.376,20.224)
  Bottom Layer w0.2: v1(35.376,20.224) 35.6,20.449 35.6,25.5 36.19,26.09 J1.3
UART0_TX: J1.2 U1.2 | length 11.6
  Top Layer w0.2: U1.2 35.2,19.2 v1(36.2,20.2)
  Bottom Layer w0.2: v1(36.2,20.2) 36,20.4 36,25.21 J1.2
UART1_CTS: J4.9 U1.8 | length 17
  Top Layer w0.2: v1(32.7,18.9) 32.8,18.8 U1.8 ; v1(42.5,19.2) 44.575,19.2 44.775,19 46.85,19 J4.9
  Bottom Layer w0.2: v1(32.7,18.9) 33.3,19.5 33.9,19.5 34.2,19.2 v1(42.5,19.2)
UART1_DSR: J4.10 U1.12 | length 19.4
  Top Layer w0.2: U1.12 31.2,19.3 31.6,19.7 v1(32.3,19.7) ; v1(42.529,20.129) 44.429,20.129 45.3,21 46.85,21 J4.10
  Bottom Layer w0.2: v1(32.3,19.7) 32.5,19.9 34.1,19.9 34.4,19.6 42,19.6 v1(42.529,20.129)
UART1_DTR: J4.6 U1.11 | length 31.8
  Top Layer w0.2: v1(31.4,16.98) 31.6,17.18 U1.11
  Bottom Layer w0.2: v1(31.4,16.98) 32.42,18 34.3,18 35.4,16.9 35.4,9.731 36.231,8.9 37.8,8.9 39,7.7 40.375,7.7 41.1,8.425 41.1,11.8 44.3,15 46.85,15 J4.6
UART1_RTS: J4.5 U1.9 | length 27.7
  Top Layer w0.2: U1.9 32.4,17.18 v1(32.58,17)
  Bottom Layer w0.2: v1(32.58,17) 33.18,17.6 34.1,17.6 35,16.7 35,9.566 36.066,8.5 37.634,8.5 38.834,7.3 43,7.3 44.669,8.969 44.669,10.231 45.436,10.998 45.497,10.998 45.5,11.001 46.852,11.001 J4.5
UART1_RX: J4.8 U1.7 | length 16.6
  Top Layer w0.2: U1.7 33.2,18.4 33.2,18.424 33.6,18.824 v1(33.6,18.9) ; v1(42.5,18.3) 44.1,18.3 45.4,17 46.85,17 J4.8
  Bottom Layer w0.2: v1(33.6,18.9) 33.7,18.8 42,18.8 v1(42.5,18.3)
UART1_TX: J4.4 U1.6 | length 24.7
  Top Layer w0.2: U1.6 33.6,17.18 v1(33.8,16.98)
  Bottom Layer w0.2: v1(33.8,16.98) 34.12,16.98 34.6,16.5 34.6,9.4 35.9,8.1 37.469,8.1 38.669,6.9 43.2,6.9 45.3,9 46.85,9 J4.4
USB_DM: J5.6 R4.1 | length 9.8
  Top Layer w0.2: R4.1 40.8,13.1 41.9,13.1 42.5,12.5 42.5,10.9 v1(42.2,10.6)
  Bottom Layer w0.2: v1(42.2,10.6) 42.2,10.617 42.5,10.917 42.5,11.466 44.234,13.2 45.05,13.2 J5.6
USB_DP: J5.5 R2.1 | length 9.8
  Top Layer w0.2: R2.1 40.8,13.5 42.066,13.5 42.9,12.666 42.9,10.9 v1(43.2,10.6)
  Bottom Layer w0.2: v1(43.2,10.6) 43.2,10.617 42.9,10.917 42.9,11.3 44.4,12.8 45.05,12.8 J5.5
XIN: C22.1 U1.20 Y1.1 | length 6.8
  Top Layer w0.2: Y1.1 24.05,15.45 24.3,15.7 27.3,15.7 C22.1 27.9,15.1 U1.20
XOUT: R7.2 U1.21 | length 2.1
  Top Layer w0.2: R7.2 27.7,14.7 U1.21
pads on no net: U1.4 U1.5 U1.17 U1.18 U1.34 U1.35 U1.36 U1.37 U2.0 U2.19 U2.34 U2.35 U2.37 U2.38 U2.39 U2.40 U2.41 U2.42 U2.43 U2.44

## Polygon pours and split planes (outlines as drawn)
GND on Bottom Layer "Top Layer-net" (solid, remove dead copper, pour order 12): 1.778,30 0,30 0,27.813 0,0 5.461,0 50,0 50,4.318 50,30 1.905,30
GND on Top Layer "Top Layer-net" (solid, remove dead copper, pour order 10): 0.889,30 0,30 0,26.289 0,0 45.466,0 50,0 50,5.207 50,30 1.016,30
3V3A on Internal Plane 2 (split plane): 18.248,16.146 18.248,0.51 0.762,0.51 0.753,0.51 0.696,0.517 0.635,0.542 0.583,0.583 0.542,0.635 0.517,0.696 0.51,0.753 0.51,0.762 0.51,9.498 13,9.498 13.065,9.506 13.126,9.532 13.178,9.572 15.082,11.475 15.175,11.475 15.175,11.568 15.178,11.572 15.218,11.624 15.244,11.685 15.252,11.75 15.252,13.25 15.244,13.315 15.218,13.376 15.196,13.406 15.178,13.428 14.002,14.604 14.002,17.146 14.604,17.748 16.646,17.748
3V3 on Internal Plane 2 (split plane): 49.304,29.483 49.365,29.458 49.417,29.417 49.458,29.365 49.483,29.304 49.49,29.247 49.49,29.238 49.49,0.762 49.49,0.753 49.483,0.696 49.458,0.635 49.417,0.583 49.365,0.542 49.304,0.517 49.247,0.51 49.238,0.51 18.752,0.51 18.752,14.248 23.4,14.248 23.4,11.7 26.2,11.7 26.2,15.3 24.002,15.3 24.002,18.75 24.002,19.5 23.994,19.565 23.968,19.626 23.928,19.678 18.678,24.928 18.626,24.968 18.565,24.994 18.5,25.002 15.5,25.002 15.435,24.994 15.374,24.968 15.322,24.928 11.822,21.428 11.782,21.376 11.756,21.315 11.748,21.25 11.748,10.002 0.51,10.002 0.51,29.238 0.51,29.247 0.517,29.304 0.542,29.365 0.583,29.417 0.635,29.458 0.696,29.483 0.753,29.49 0.762,29.49 49.238,29.49 49.247,29.49
1V2D on Internal Plane 2 (split plane): 23.498,19.396 23.498,18.75 23.498,15.3 23.4,15.3 23.4,14.752 18.752,14.752 18.752,16.25 18.744,16.315 18.718,16.376 18.678,16.428 16.928,18.178 16.876,18.218 16.815,18.244 16.75,18.252 14.5,18.252 14.435,18.244 14.374,18.218 14.322,18.178 13.572,17.428 13.532,17.376 13.506,17.315 13.498,17.25 13.498,14.5 13.506,14.435 13.532,14.374 13.572,14.322 14.748,13.146 14.748,12.075 14.55,12.075 14.55,11.657 12.896,10.002 12.252,10.002 12.252,21.146 15.604,24.498 18.396,24.498
1V1 on Internal Plane 2 (split plane): 39.498,16.646 39.498,15.354 39.146,15.002 37.25,15.002 37.185,14.994 37.124,14.968 37.072,14.928 34.396,12.252 30.354,12.252 29.752,12.854 29.752,15.146 31.604,16.998 39.146,16.998
GND on Internal Plane 1 (split plane): 49.304,29.483 49.365,29.458 49.417,29.417 49.458,29.365 49.483,29.304 49.49,29.247 49.49,29.238 49.49,0.762 49.49,0.753 49.483,0.696 49.458,0.635 49.417,0.583 49.365,0.542 49.304,0.517 49.247,0.51 49.238,0.51 0.762,0.51 0.753,0.51 0.696,0.517 0.635,0.542 0.583,0.583 0.542,0.635 0.517,0.696 0.51,0.753 0.51,0.762 0.51,29.238 0.51,29.247 0.517,29.304 0.542,29.365 0.583,29.417 0.635,29.458 0.696,29.483 0.753,29.49 0.762,29.49 49.238,29.49 49.247,29.49

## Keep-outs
Keep-Out Layer:
  the board outline again, w0.127
  text ".Layer_Name" at 9.398,31.75 h1.52

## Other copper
Top Layer:
  pour cut-out: 1.15,16 ccw(c2.15,16) 2.15,15 ccw(c2.15,16) 3.15,16 ccw(c2.15,16) 2.15,17 ccw(c2.15,16)
  pour cut-out: 1.15,10 ccw(c2.15,10) 2.15,9 ccw(c2.15,10) 3.15,10 ccw(c2.15,10) 2.15,11 ccw(c2.15,10)
  pour cut-out: 44.85,26 ccw(c45.85,26) 45.85,25 ccw(c45.85,26) 46.85,26 ccw(c45.85,26) 45.85,27 ccw(c45.85,26)
  pour cut-out: 46.85,24 ccw(c47.85,24) 47.85,23 ccw(c47.85,24) 48.85,24 ccw(c47.85,24) 47.85,25 ccw(c47.85,24)
  pour cut-out: 46.85,16 ccw(c47.85,16) 47.85,15 ccw(c47.85,16) 48.85,16 ccw(c47.85,16) 47.85,17 ccw(c47.85,16)
  pour cut-out: 46.85,8 ccw(c47.85,8) 47.85,7 ccw(c47.85,8) 48.85,8 ccw(c47.85,8) 47.85,9 ccw(c47.85,8)
  pour cut-out: 44.85,4 ccw(c45.85,4) 45.85,3 ccw(c45.85,4) 46.85,4 ccw(c45.85,4) 45.85,5 ccw(c45.85,4)
  region net 3V3: 19.5,9.5 19.1,9.1 19.1,8.2 19.5,7.8 20.4,7.8 20.8,8.2 20.8,9.1 20.4,9.5
  region net 3V3A: 14.6,9.5 14.2,9.1 14.2,8.2 14.6,7.8 15.5,7.8 15.9,8.2 15.9,9.1 15.5,9.5
  pour cut-out: 20.7,0.35 20.875,0.525 20.875,0.775 20.775,0.875 20.925,0.875 49.725,0.875 49.725,0.35
  text ".Layer_Name" at 9.398,31.75 h1.52
Bottom Layer:
  pour cut-out: 3.15,16 cw(c2.15,16) 2.15,15 cw(c2.15,16) 1.15,16 cw(c2.15,16) 2.15,17 cw(c2.15,16)
  pour cut-out: 3.15,10 cw(c2.15,10) 2.15,9 cw(c2.15,10) 1.15,10 cw(c2.15,10) 2.15,11 cw(c2.15,10)
  pour cut-out: 46.85,26 cw(c45.85,26) 45.85,25 cw(c45.85,26) 44.85,26 cw(c45.85,26) 45.85,27 cw(c45.85,26)
  pour cut-out: 48.85,24 cw(c47.85,24) 47.85,23 cw(c47.85,24) 46.85,24 cw(c47.85,24) 47.85,25 cw(c47.85,24)
  pour cut-out: 48.85,16 cw(c47.85,16) 47.85,15 cw(c47.85,16) 46.85,16 cw(c47.85,16) 47.85,17 cw(c47.85,16)
  pour cut-out: 48.85,8 cw(c47.85,8) 47.85,7 cw(c47.85,8) 46.85,8 cw(c47.85,8) 47.85,9 cw(c47.85,8)
  pour cut-out: 46.85,4 cw(c45.85,4) 45.85,3 cw(c45.85,4) 44.85,4 cw(c45.85,4) 45.85,5 cw(c45.85,4)
  region net 3V3: 38,13.8 38.3,14.1 38.3,14.5 38,14.8 38,15.1 36.6,15.1 36.6,14.1 36.9,13.8 37.2,13.8
  region net 3V3: 17.8,9.1 18.2,9.5 20.4,9.5 20.8,9.1 20.8,8.2 20.4,7.8 18.2,7.8 17.8,8.2 17.8,8.8
  region net 3V3A: 17.2,9.1 16.8,9.5 14.6,9.5 14.2,9.1 14.2,8.2 14.6,7.8 16.8,7.8 17.2,8.2 17.2,8.8
  text ".Layer_Name" at 9.398,31.75 h1.52
Internal Plane 1 (plane layer: these items are gaps in the copper):
  text "GND" at 9.398,31.782 h1.52
Internal Plane 2 (plane layer: these items are gaps in the copper):
  pour cut-out: 23.4,15.3 23.4,11.7 26.2,11.7 26.2,15.3
  pour cut-out: 7.1,14.8 7.1,11.2 9.9,11.2 9.9,14.8
  pour cut-out: 14.55,12.075 15.175,12.075 15.175,11.475 14.55,11.475
  lines w0.5: 0,9.75 13,9.75 15,11.75 ; 12,9.75 12,21.25 15.5,24.75 18.5,24.75 23.75,19.5 23.75,18.75 23.75,14.55 23.7,14.5 18.5,14.5 ; 18.5,0 18.5,16.25 16.75,18 14.5,18 13.75,17.25 13.75,14.5 15,13.25 15,11.75 ; 15,11.75 15,11.75 ; 29.5,12.75 30.25,12 34.5,12 37.25,14.75 38.25,14.75 39.25,14.75 39.75,15.25 39.75,16.75 39.25,17.25 31.5,17.25 29.5,15.25 29.5,12.75
  text "POWER" at 9.398,31.782 h1.52

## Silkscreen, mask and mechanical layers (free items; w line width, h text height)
Top Overlay:
  rectangle: 3.4,0.325 29.4,7.325
  lines w0.127: 49.492,-0.009 ccw(c49.511,0.264) 49.784,0.254 ; 0.127,0.254 ccw(c0.381,0.254) 0.381,0 49.53,0 49.657,0.127 ; 0.127,0.254 0.254,0.127 49.657,0.127 ; 0.127,0.254 49.784,0.254 ; 49.657,0.127 49.784,0.254
  text ".Layer_Name" at 9.398,31.782 h1.52
  text "10" at 43.434,21.717 h0.64
  text "9" at 3.556,19.685 h0.64
  text "5" at 3.556,11.684 h0.64
  text "5" at 43.942,11.684 h0.64
  text "WIZ500SR-RP V100" at 3.7,7.6 h2
  text "RESET" at 30.393,7.4 h0.8
Bottom Overlay:
  lines w0.2: 8.25,1 17.5,1 ; 8.25,2.5 17.5,2.5 ; 8.25,4 17.5,4 ; 19.75,1.75 23.25,1.75 ; 26.75,0.25 26.75,1.75 26.75,14.25 ; 23.25,0.25 30.75,0.25 30.75,1.75 ; 23.25,0.25 23.25,1.75 ; 23.25,0.25 19.75,0.25 19.75,14.25 23.25,14.25 ; 23.25,1.75 23.25,14.25 ; 23.25,1.75 30.75,1.75 ; 23.25,14.25 30.75,14.25 30.75,1.75
  text ".Layer_Name" at 9.398,31.75 h1.52
  text "5" at 30.799,29.074 h0.64 r270
  text "10" at 4.5,21.75 h0.64
  text "10" at 44.25,21.75 h0.64
  text "3V3" at 22.479,13.15 h0.8
  text "GND" at 26.021,13.15 h0.8
  text "BLINK" at 30.106,13.15 h0.8
  text "COLn" at 22.778,12.15 h0.8
  text "IO27" at 26.105,12.15 h0.8
  text "GND" at 29.771,12.15 h0.8
  text "5" at 4.25,11.75 h0.64
  text "5" at 44.25,11.5 h0.64
  text "ACTn" at 22.82,11.15 h0.8
  text "IO26" at 26.085,11.15 h0.8
  text "DSR1" at 29.914,11.15 h0.8
  text "SPDn" at 22.778,10.15 h0.8
  text "HWT" at 26.105,10.15 h0.8
  text "CTS1" at 29.914,10.15 h0.8
  text "LINKn" at 22.799,9.15 h0.8
  text "FACT" at 26.356,9.15 h0.8
  text "RXD1" at 29.914,9.15 h0.8
  text "GND" at 22.521,8.15 h0.8
  text "PREV" at 26.331,8.15 h0.8
  text "GND" at 29.771,8.15 h0.8
  text "TXP" at 22.437,7.15 h0.8
  text "DM" at 25.661,7.15 h0.8
  text "DTR1" at 29.872,7.15 h0.8
  text "TXN" at 22.437,6.15 h0.8
  text "DP" at 25.623,6.15 h0.8
  text "RTS1" at 29.872,6.15 h0.8
  text "GND" at 22.521,5.15 h0.8
  text "BOOT" at 26.419,5.15 h0.8
  text "TXD1" at 29.872,5.15 h0.8
  text "WIZ500SR-RP" at 17.5,4.25 h1.2
  text "RXP" at 22.479,4.15 h0.8
  text "TCP" at 25.979,4.15 h0.8
  text "GND" at 29.771,4.15 h0.8
  text "1" at 4,3.5 h0.64
  text "1" at 44,3.5 h0.64
  text "RXN" at 22.479,3.15 h0.8
  text "LINK" at 26,3.15 h0.8
  text "RESET" at 30.357,3.15 h0.8
  text "http://wiznet.io" at 17.5,3 h1
  text "3V3" at 22.479,2.15 h0.8
  text "GND" at 26.021,2.15 h0.8
  text "3V3" at 29.729,2.15 h0.8
  text "Designed by WIZnet" at 17.5,1.5 h1
  text "J3" at 22.35,0.65 h0.8
  text "J5" at 25.85,0.65 h0.8
  text "J4" at 29.35,0.65 h0.8
Top Paste:
  text ".Layer_Name" at 9.398,31.75 h1.52
Bottom Paste:
  text ".Layer_Name" at 9.398,31.75 h1.52
Top Solder:
  text ".Layer_Name" at 9.398,31.75 h1.52
Bottom Solder:
  text ".Layer_Name" at 9.398,31.75 h1.52
Drill Guide:
  text ".Layer_Name" at 9.398,31.75 h1.52
Mechanical 2:
  lines w0.127: 54.432,12.065 80.594,12.065 ; 54.432,14.859 80.594,14.859 ; 0,0.762 ccw(c0.762,0.762) 0.762,0 49.238,0 ccw(c49.238,0.762) 50,0.762 50,29.238 ccw(c49.238,29.238) 49.238,30 0.762,30 ccw(c0.762,29.238) 0,29.238 0,0.762 ; 53.086,0.711 ccw(c53.797,0.711) 53.797,0 80.975,0 ccw(c80.975,0.711) 81.686,0.711 81.686,19.939 ccw(c80.975,19.939) 80.975,20.65 53.797,20.65 ccw(c53.797,19.939) 53.086,19.939 53.086,0.711
  text "BOARD NAME : WIZ500SR-RP_V100" at 0,42.926 h1.52
  text "VERSION : V100" at 0,40.132 h1.52
  text "SIZE : 50mmX30mmX1.6T" at 0,37.338 h1.52
  text "GERBER DATE : 2022.05.03." at 0,34.544 h1.52
  text "LAYER :" at 0,31.75 h1.52
  text "Layer Stack Up Detail for:" at 54.559,18.542 h1.02
  text "WIZ500SR-RP_V100.PcbDoc" at 54.432,16.129 h1.27
  text "Layer Name : 4L  1.6T" at 54.559,12.954 h1.02
  text "Top Layer" at 54.432,9.271 h1.52
  text "GND" at 54.432,6.477 h1.52
  text "POWER" at 54.432,3.81 h1.52
  text "Bottom Layer" at 54.432,1.27 h1.52
  text "KS Technology artwork" at 53.086,-4.064 h5.08
Drill Drawing:
  text ".Layer_Name" at 9.398,31.75 h1.52
  text ".Legend" at 55.118,23.368 h1.02

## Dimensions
0.762,0 to 0.762,30 on Mechanical 2
0,0.762 to 50,0.762 on Mechanical 2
